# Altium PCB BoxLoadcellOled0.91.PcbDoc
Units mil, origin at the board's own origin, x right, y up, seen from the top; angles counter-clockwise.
Board outline 2350 x 1500 mil, 2 copper layers (Top Layer, Bottom Layer); 17 components, 32 nets, 99 pads, 0 vias.
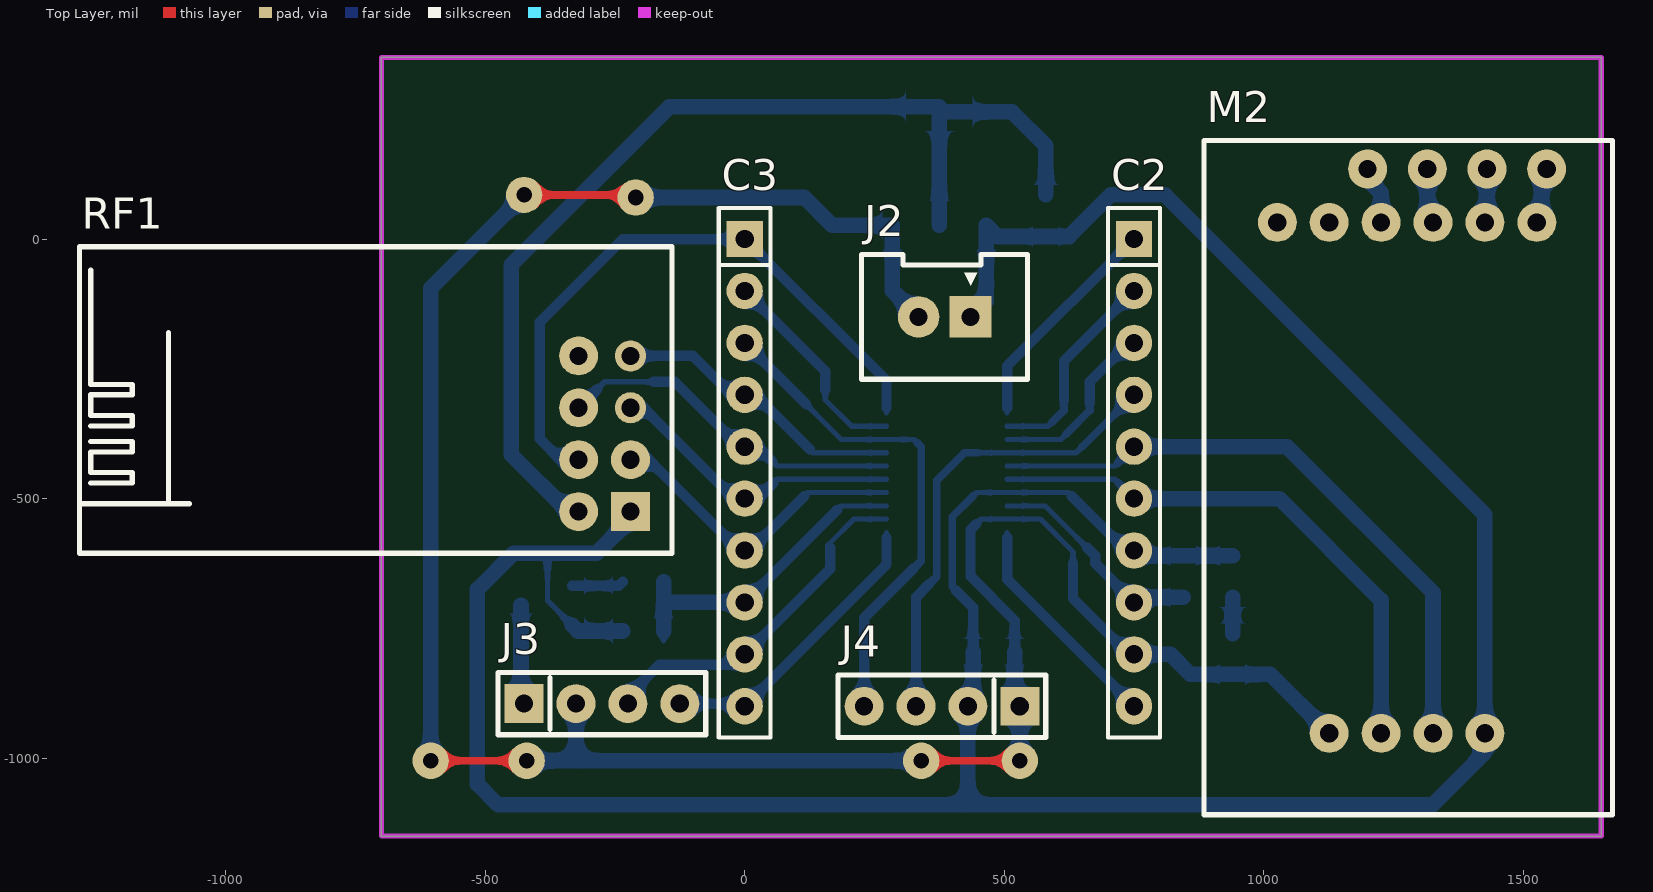
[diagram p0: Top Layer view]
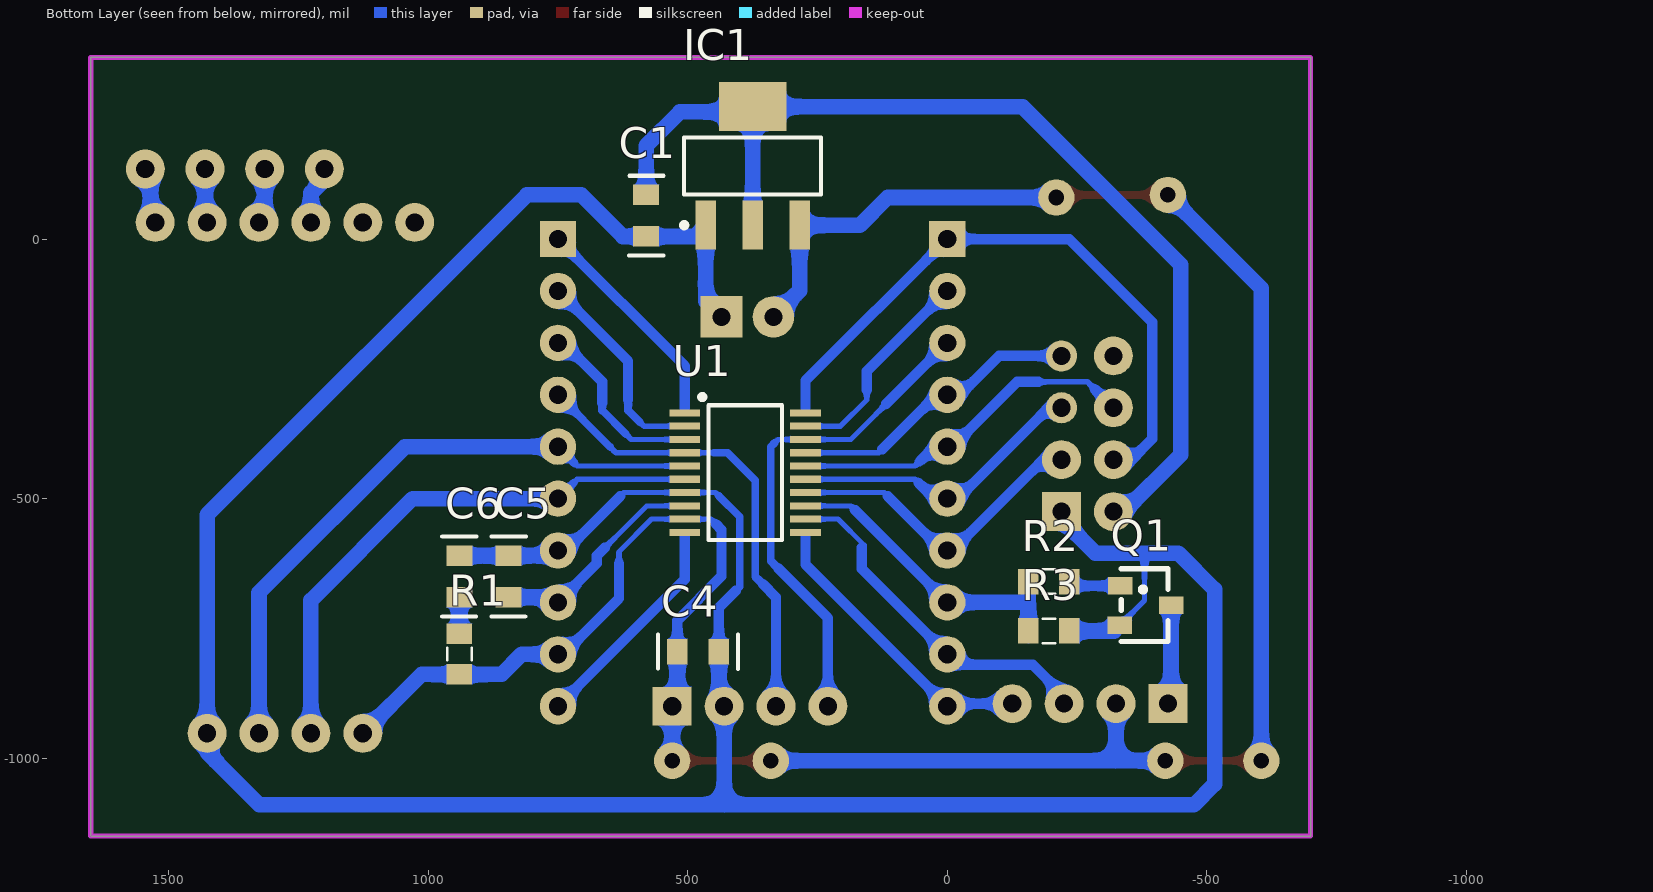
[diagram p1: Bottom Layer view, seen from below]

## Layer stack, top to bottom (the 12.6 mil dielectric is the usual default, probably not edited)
Top Solder: solder mask 0.4, Solder Resist, Dk 3.5
Top Layer: signal copper 1.4
Dielectric 1: dielectric 12.6, FR-4, Dk 4.8
Bottom Layer: signal copper 1.4
Bottom Solder: solder mask 0.4, Solder Resist, Dk 3.5

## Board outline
-700,-1150 -700,350 1650,350 1650,-1150

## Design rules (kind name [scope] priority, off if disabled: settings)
Clearance [All] p1: gap=10 ignorepadtopadclearanceinfootprint=FALSE except(0: Arc-Hole Track-Hole SMDPad-Hole THPad-Hole Via-Hole Fill-Hole Poly-Hole Region-Hole Text-Hole)
PolygonConnect [All] p1: connectstyle=Relief reliefconductorwidth=10 reliefentries=4 polygonreliefangle="90 Angle" airgapwidth=10
RoutingVias [All] p1: holewidth=28 width=50 viastyle="Through Hole" minholewidth=28 minwidth=50 maxholewidth=28 maxwidth=50
SolderMaskExpansion [All] p1: expansion=4
Width [All] p1: maxlimit=20 minlimit=10 preferedwidth=15
30 further rules are at their usual default settings.

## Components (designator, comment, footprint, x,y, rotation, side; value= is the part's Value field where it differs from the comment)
C1 "104" C0805 580,45 r90 bottom value=33p
C2 "JP10" JP10-C1T 750,0 r270 top
C3 "JP10" JP10-C1T 0,0 r270 top
C4 "104" C0805 480,-795 r0 bottom value=33p
C5 "105" C0805 845,-650 r270 bottom value=33p
C6 "104" C0805 940,-650 r270 bottom value=33p
IC1 "AMS_1117" SOT_223_2 375,140.83 r90 bottom
J2 "Jump_2" XH2.54-2P 435,-150 r180 top
J3 "Jump_4" Jump_4 -425,-895 r90 top
J4 "Jump_4" Jump_4 530,-900 r270 top
M2 "Module HX711" "Module HX711" 1275,-460 r270 top
Q1 "C1815" "SOT_23 - 321" -430,-705 r270 bottom
R1 "10K" RES-0805 940,-760 r90 bottom value=1K
R2 "4K7" RES-0805 -235,-660 r180 bottom value=1K
R3 "4K7" RES-0805 -156.26,-755 r0 bottom value=1K
RF1 "RF24L01" RF24L01 -340,-310 r0 top
U1 "STM8S003F3P6" TSSOP20 389.37,-450 r180 bottom

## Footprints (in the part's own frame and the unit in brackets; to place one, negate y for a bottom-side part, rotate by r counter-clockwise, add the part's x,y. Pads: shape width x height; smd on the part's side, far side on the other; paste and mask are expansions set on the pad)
C0805 [mil] "Chip Resistor; Body 2.0 x 1.3 mm (LxW typ)"
  rect 39.37x50 smd: 1(-40,0) 2(40,0)
  silkscreen extent -77,-33 77,33, body extent -39,-25 39,25, height 31
JP10-C1T [mil] "10 row, straight, gold plating"
  rect 70x70 hole 35: 1(0,0)
  round 70 hole 35: 2(100,0) 3(200,0) 4(300,0) 5(400,0) 6(500,0) 7(600,0) 8(700,0) 9(800,0) 10(900,0)
  silkscreen extent -60,-50 960,50, body extent -60,-49 960,49, height 335
Jump_4 [mil] "Jump_4 Pin 2.54"
  rect 75x75 hole 35: 1(0,0)
  round 75 hole 35: 2(0,-100) 3(0,-200) 4(0,-300)
  silkscreen extent -60,-350 60,50, body extent -53,-353 53,53, height 346
"Module HX711" [mil] "Module HX711"
  round 75 hole 35: 1(-492.13,251) 2(-492.13,151) 3(-492.13,51) 4(-492.13,-49) 5(-492.13,-149) 6(-492.13,-249) 7(492.13,-149) 8(492.13,-49) 9(492.13,51) 10(492.13,151)
  silkscreen extent -650,-390 649,397
RES-0805 [mm] "Chip Resistor; Body 2 x 1.2 mm (LxW typ)"
  rect 1x1.25 smd: 1(0,0) 2(-2,0)
  silkscreen extent -1.3,-0.6 -0.7,0.6, body extent -2,-0.6 0,0.6, height 0.7
RF24L01 [mil] "Module RF24L01"
  rect 75x75 hole 35: 1(120,-215)
  round 75 hole 35: 2(20,-215) 3(120,-115) 4(20,-115) 6(20,-15) 8(20,85)
  round 60 hole 35: 5(120,-15) 7(120,85)
  silkscreen extent -942,-295 200,295, body extent -942,-300 200,290, height 138
"SOT_23 - 321" [mm] "SOT 23 _ 3-2-1_TO236"
  rect 0.85x1.2 smd: 1(0.985,-2.474) 2(0.005,0.026) 3(-0.94,-2.469)
  silkscreen extent -1.78,-2.41 1.78,-0.13, body extent -1.47,-2.55 1.53,-0.05, height 1.06
SOT_223_2 [mm] "SOT223, 4-Leads, Body 6.5x3.5mm, Pitch 2.3mm, Lead Span 7mm, IPC Medium Density"
  rect 2.4x1 smd: 1(-2.9,2.3) 2(-2.9,0) 3(-2.9,-2.3)
  rect 2.4x3.3 smd: 2(2.9,0)
  silkscreen extent -3.02,-3.35 1.4,3.48, body extent -3.39,-3.27 3.5,3.23, height 1.72
TSSOP20 [mm] "TSOP, 20-Leads, Body 6.5x4.4mm, Pitch 0.65mm, IPC Medium Density"
  rect 1.5x0.35 smd: 1(-2.95,2.925) 2(-2.95,2.275) 3(-2.95,1.625) 4(-2.95,0.975) 5(-2.95,0.325) 6(-2.95,-0.325) 7(-2.95,-0.975) 8(-2.95,-1.625) 9(-2.95,-2.275) 10(-2.95,-2.925) 11(2.95,-2.925) 12(2.95,-2.275) 13(2.95,-1.625) 14(2.95,-0.975) 15(2.95,-0.325) 16(2.95,0.325) 17(2.95,0.975) 18(2.95,1.625) 19(2.95,2.275) 20(2.95,2.925)
  silkscreen extent -2.23,-3.3 1.8,3.82, body extent -3.2,-3.25 3.2,3.25, height 1.2
XH2.54-2P [mil] "Pin XH 2.54 2P"
  rect 80x80 hole 35: 1(0,0)
  round 80 hole 35: 2(100,0)
  silkscreen extent -110,-120 210,120, body extent -108,-118 206,118, height 276

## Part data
C1 C4 C5 C6: library part CapSMD, "Capacitor"
C2 C3: "WR-PHD 2.54 mm Angled Socket Header", Manufacturer="Würth Elektronik eiSos GmbH", partNo=613010143121
IC1: "IC Power"
J2: "Jump_2 Pin 2.54"
Q1: "NPN 600mW, ECB"
R1 R2 R3: library part RES, "Resistor SMD"
RF1: "Module RF24L01"

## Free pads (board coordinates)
  round 75 hole 35: 2(1200,135) 2(1315,135) 2(1430,135) 2(1545,135)
  round 70 hole 30: 3(-605,-1005) 3(-425,85) 3(-420,-1005) 3(-210,80) 3(340,-1005) 3(530,-1005)

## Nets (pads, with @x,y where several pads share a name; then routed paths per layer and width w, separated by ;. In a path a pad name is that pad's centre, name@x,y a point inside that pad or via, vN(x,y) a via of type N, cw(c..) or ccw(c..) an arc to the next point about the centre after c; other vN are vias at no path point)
1: C2.1 U1.1 | length 436.1
  Bottom Layer w10: U1.1 505.51,-325
  Bottom Layer w20: 505.51,-325 505.51,-244.49 C2.1
2: C2.2 U1.2 | length 408
  Bottom Layer w10: U1.2 584.57,-360.43 592.5,-352.5
  Bottom Layer w15: 592.5,-352.5 615,-330 615,-310
  Bottom Layer w20: 615,-310 615,-235 C2.2
3: C2.3 U1.3 | length 353.8
  Bottom Layer w10: U1.3 608.98,-386.02 620,-375
  Bottom Layer w15: 620,-375 665,-330 665,-315
  Bottom Layer w20: 665,-315 665,-275 740,-200 C2.3
4: C2.4 J4.3 U1.4 | length 899.9
  Bottom Layer w10: 450,-411.61 U1.4 638.39,-411.61 650,-400
  Bottom Layer w15: 355,-665 370,-650 370,-465 423.39,-411.61 450,-411.61 ; 650,-400 C2.4
  Bottom Layer w20: J4.3 330,-690 355,-665
5: C2.5 M2.9 U1.5 | length 1223.4
  Bottom Layer w10: U1.5 712.8,-437.2 717.5,-432.5
  Bottom Layer w15: 717.5,-432.5 C2.5
  Bottom Layer w30: C2.5 1045,-400 1326,-681 M2.9
6: C2.6 M2.8 U1.6 | length 1073.2
  Bottom Layer w10: U1.6 712.8,-462.8 720,-470
  Bottom Layer w15: 720,-470 C2.6
  Bottom Layer w30: C2.6 1030,-500 1226,-696 M2.8
7: C1.1 C2.7 C4.1 C5.1 C6.1 IC1.1 J2.1 J4.2 M2.10 Q1.1 R3.2 RF1.1 U1.7 | length 6091.4
  Bottom Layer w10: -380,-635 -380,-696.4 Q1.1 ; 440,-495 446.61,-488.39 U1.7 623.39,-488.39 630,-495
  Bottom Layer w15: -380,-635 -380,-605 ; 407.5,-677.5 400,-670 400,-535 440,-495
  Bottom Layer w20: 407.5,-677.5 440,-710 C4.1 ; 630,-495 735,-600 C2.7
  Bottom Layer w30: Q1.1 -321.4,-755 R3.2 ; RF1.1 -220,-540 -285,-605 -380,-605 -445,-605 -515,-675 -515,-1050 -475,-1090 430,-1090 ; J2.1 465.55,-119.45 IC1.1 487.2,5 C1.1 625,5 705,85 810,85 1426,-531 M2.10 1426,-989 1325,-1090 430,-1090 ; C4.1 440,-890 J4.2 430,-1090 ; C2.7 760,-610 C5.1 C6.1
8: C2.8 C5.2 U1.8 | length 429.5
  Bottom Layer w10: U1.8 578.98,-513.98 660,-595
  Bottom Layer w20: 660,-595 675,-610 675,-625 C2.8
  Bottom Layer w30: C2.8 760,-690 C5.2
10: C2.10 U1.10 | length 436.1
  Bottom Layer w10: 505.51,-575 U1.10
  Bottom Layer w20: 505.51,-575 505.51,-655.51 C2.10
11: C3.10 J3.4 U1.11 | length 575.1
  Bottom Layer w10: 273.23,-575 U1.11
  Bottom Layer w20: J3.4 C3.10@-5,-895 ; C3.10 273.23,-626.77 273.23,-575
  Bottom Layer w30: C3.10@-5,-895 C3.10
12: C3.9 J3.3 U1.12 | length 680.6
  Bottom Layer w10: 160,-590 210.43,-539.57 U1.12
  Bottom Layer w20: J3.3 -225,-880 -165,-820 -20,-820 C3.9 165,-635 165,-595
13: C3.8 R2.2 R3.1 U1.13 | length 622.9
  Bottom Layer w10: R3.1@-156.26,-773.74 R3.1 ; 177.5,-522.5 186.02,-513.98 U1.13
  Bottom Layer w20: C3.8 177.5,-522.5
  Bottom Layer w30: R3.1 -156.26,-693.74 ; R2.2 -156.26,-693.74 ; C3.8 -150,-700 -156.26,-693.74
14: C3.7 RF1.3 U1.14 | length 611.9
  Bottom Layer w10: 115,-495 121.61,-488.39 U1.14
  Bottom Layer w20: RF1.3 -185,-425 -10,-600 C3.7 10,-600 115,-495
15: C3.6 RF1.5 U1.15 | length 581.1
  Bottom Layer w10: 55,-470 62.2,-462.8 U1.15
  Bottom Layer w20: RF1.5 -195,-325 -20,-500 C3.6 25,-500 55,-470
16: C3.5 RF1.6 U1.16 | length 681.1
  Bottom Layer w10: -285,-290 -270,-275 -175,-275 ; 52.5,-427.5 62.2,-437.2 U1.16
  Bottom Layer w20: RF1.6 -285,-290 ; -175,-275 -135,-275 -10,-400 C3.5 25,-400 52.5,-427.5
17: C3.4 RF1.7 U1.17 | length 570.5
  Bottom Layer w10: 125,-405 131.61,-411.61 U1.17
  Bottom Layer w20: RF1.7 -100,-225 -25,-300 C3.4 20,-300 125,-405
18: C3.3 J4.4 U1.18 | length 968.4
  Bottom Layer w10: 117.5,-317.5 186.02,-386.02 U1.18 326.02,-386.02 333.01,-393.01
  Bottom Layer w15: 325,-635 340,-620 340,-400 333.01,-393.01
  Bottom Layer w20: C3.3 117.5,-317.5 ; J4.4 230,-730 325,-635
19: C3.2 U1.19 | length 413.3
  Bottom Layer w10: 155,-290 155,-310 205.43,-360.43 U1.19
  Bottom Layer w20: C3.2 155,-255 155,-290
20: C3.1 RF1.4 U1.20 | length 1225.9
  Bottom Layer w10: U1.20 273.23,-325
  Bottom Layer w20: RF1.4 -355,-425 -395,-385 -395,-160 -235,0 C3.1 273.23,-273.23 273.23,-325
+3V3: C1.2 IC1.2 RF1.2 | length 2047.2
  Bottom Layer w30: RF1.2 -340,-525 -450,-415 -450,-50 -145,255 375,255 IC1.2@375,245 ; IC1.2@375,26.65 IC1.2@375,245 ; C1.2 580,180 515,245 IC1.2@375,245
+5V: C2.9 C4.2 IC1.3 J2.2 J3.2 J4.1 M2.7 pad.3 R1.2 U1.9 | length 4748.2
  Top Layer w15: pad.3@-605,-1005 pad.3@-420,-1005 ; pad.3@-425,85 -215,85 pad.3@-210,80 ; pad.3@340,-1005 pad.3@530,-1005
  Bottom Layer w10: 445.22,-549.78 455.43,-539.57 U1.9 569.57,-539.57 632.5,-602.5 632.5,-625
  Bottom Layer w20: 445.22,-549.78 435,-560 435,-650 520,-735 C4.2 ; 632.5,-625 632.5,-692.5 740,-800 C2.9
  Bottom Layer w30: pad.3@-605,-1005 -605,-95 pad.3@-425,85 ; pad.3@-420,-1005 -325,-1005 ; J3.2 -325,-1005 ; pad.3@-210,80 115,80 168.35,26.65 IC1.3 284.45,-99.45 J2.2 ; pad.3@340,-1005 -325,-1005 ; C4.2 520,-890 J4.1 pad.3@530,-1005 ; C2.9 820,-800 858.74,-838.74 R1.2 1012.61,-838.74 M2.7
-LCD: J3.1 Q1.2 | length 192.3
  Bottom Layer w30: Q1.2 -431.02,-888.98 J3.1
BLACK: M2.2 pad.2@1430,135 | length 104.5
  Bottom Layer w30: M2.2 1430,36.13 pad.2@1430,135
DQ: 
DT_Loadcell: 
NetQ1_3: Q1.3 R2.1 | length 101.1
  Bottom Layer w20: Q1.3 -243,-668 R2.1
NRST: C6.2 R1.1 | length 70
  Bottom Layer w30: R1.1 C6.2
PD3: 
RED: M2.1 pad.2@1545,135 | length 110.7
  Bottom Layer w30: M2.1 1535,41.13 1535,125 pad.2@1545,135
SCK_Loadcell: 
WHITE: M2.3 pad.2@1315,135 | length 107.4
  Bottom Layer w30: pad.2@1315,135 1315,43.13 M2.3
YELLOW: M2.4 pad.2@1200,135 | length 113.6
  Bottom Layer w30: pad.2@1200,135 1200,115 1226,89 M2.4
pads on no net: M2.5 M2.6 RF1.8

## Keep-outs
Keep-Out Layer:
  lines w10: -700,-1150 -700,350 -650,350 1650,350 1650,-1150 -700,-1150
